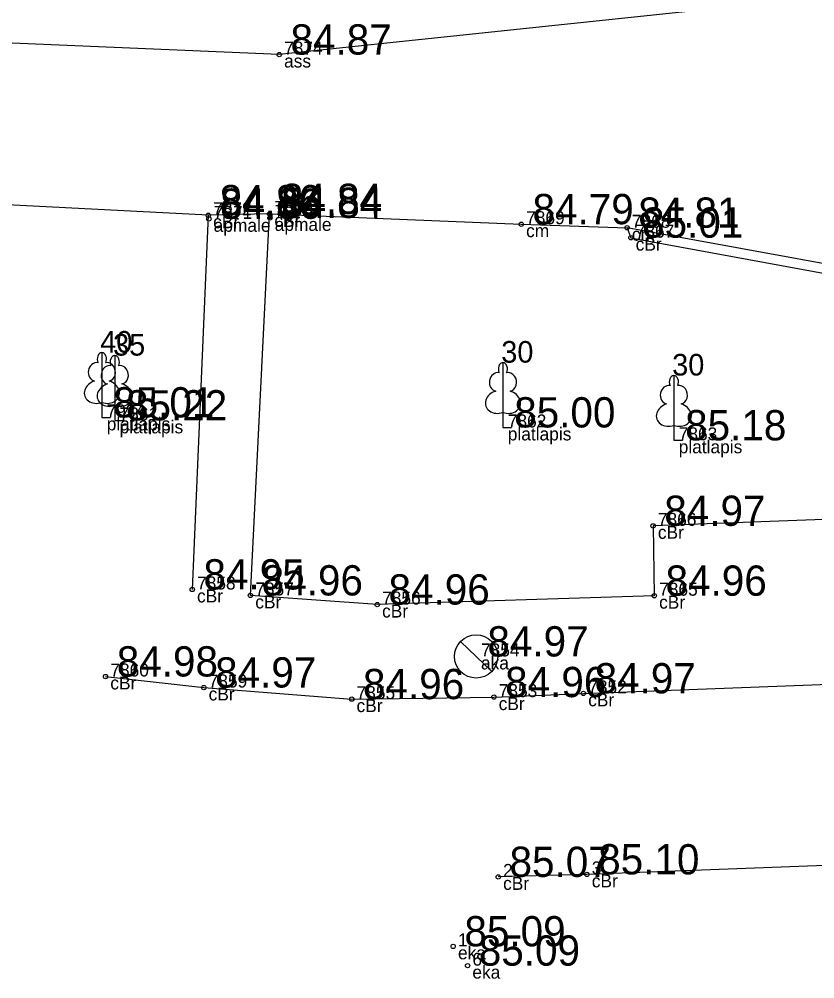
# Model space of a CAD drawing. Extents: x 614911 to 615803, y 262110 to 264311.
# Drawn here: x 615091.66 to 615110.07, y 262498.43 to 262520.64 of the extents above; entities that cross this region are included whole.
import ezdxf

# ---------------------------------------------------------------- set-up
doc = ezdxf.new("R2010")
doc.units = 0
for name, color, linetype in [('Level 1', 7, 'Continuous'), ('Level 12', 7, 'Continuous'), ('Level 37', 7, 'Continuous'), ('Level 53', 7, 'Continuous'), ('Level 54', 7, 'Continuous'), ('Level 57', 7, 'Continuous'), ('Level 58', 7, 'Continuous')]:
    doc.layers.add(name, color=color, linetype=linetype)

msp = doc.modelspace()

# ---------------------------------------------------------------- linework, layer by layer
at = {"layer": 'Level 1'}
for p, q in [((615093.575, 262511.768), (615093.575, 262511.421)), ((615093.873, 262511.699), (615093.873, 262511.352)), ((615102.855, 262511.536), (615102.855, 262511.189)), ((615093.575, 262511.421), (615093.775, 262511.421)), ((615093.873, 262511.352), (615094.073, 262511.352)), ((615102.855, 262511.189), (615103.055, 262511.189)), ((615106.81, 262511.238), (615106.81, 262510.891)), ((615106.81, 262510.891), (615107.01, 262510.891))]:
    msp.add_line(p, q, dxfattribs=at)
for points in [[(615093.575, 262512.921), (615093.575, 262511.768)], [(615093.873, 262512.852), (615093.873, 262511.699)], [(615093.665, 262512.689), (615093.664, 262512.69)], [(615093.963, 262512.62), (615093.962, 262512.621)], [(615102.855, 262512.689), (615102.855, 262511.536)], [(615102.945, 262512.457), (615102.944, 262512.458)], [(615106.81, 262512.391), (615106.81, 262511.238)], [(615106.9, 262512.159), (615106.899, 262512.16)]]:
    msp.add_lwpolyline(points, dxfattribs=at)
for centre, major_axis, ratio, start_param, end_param in [((615093.575, 262512.771), (0, -0.15), 0.707107, 3.14537, 5.287485), ((615093.575, 262512.771), (0, -0.15), 0.707107, 0.995701, 3.137816), ((615093.873, 262512.702), (0, -0.15), 0.707107, 3.14537, 5.287485), ((615093.873, 262512.702), (0, -0.15), 0.707107, 0.995701, 3.137816), ((615093.447, 262512.476), (-0.039, -0.212), 0.861323, 3.141593, 6.283185), ((615093.745, 262512.407), (-0.039, -0.212), 0.861323, 3.141593, 6.283185), ((615093.703, 262512.476), (0.039, -0.212), 0.861323, 0, 3.141593), ((615094.001, 262512.407), (0.039, -0.212), 0.861323, 0, 3.141593), ((615102.855, 262512.539), (0, -0.15), 0.707107, 3.14537, 5.287485), ((615102.855, 262512.539), (0, -0.15), 0.707107, 0.995701, 3.137816), ((615102.727, 262512.244), (-0.039, -0.212), 0.861323, 3.141593, 6.283185), ((615102.983, 262512.244), (0.039, -0.212), 0.861323, 0, 3.141593), ((615106.81, 262512.241), (0, -0.15), 0.707107, 3.14537, 5.287485), ((615106.81, 262512.241), (0, -0.15), 0.707107, 0.995701, 3.137816), ((615093.485, 262512.014), (0.307, 0.095), 0.814445, 1.570796, 4.752015), ((615093.783, 262511.945), (0.307, 0.095), 0.814445, 1.570796, 4.752015), ((615093.665, 262512.014), (-0.307, 0.095), 0.814445, 1.531171, 4.712389), ((615093.963, 262511.945), (-0.307, 0.095), 0.814445, 1.531171, 4.712389), ((615106.682, 262511.946), (-0.039, -0.212), 0.861323, 3.141593, 6.283185), ((615106.938, 262511.946), (0.039, -0.212), 0.861323, 0, 3.141593), ((615102.765, 262511.782), (0.307, 0.095), 0.814445, 1.570796, 4.752015), ((615102.945, 262511.782), (-0.307, 0.095), 0.814445, 1.531171, 4.712389), ((615106.72, 262511.484), (0.307, 0.095), 0.814445, 1.570796, 4.752015), ((615106.9, 262511.484), (-0.307, 0.095), 0.814445, 1.531171, 4.712389)]:
    msp.add_ellipse(centre, major_axis=major_axis, ratio=ratio, start_param=start_param, end_param=end_param, dxfattribs=at)
at = {"layer": 'Level 12'}
for p, q in [((615101.876, 262506.237), (615102.594, 262505.541)), ((615102.235, 262505.889), (615102.234, 262505.888))]:
    msp.add_line(p, q, dxfattribs=at)
msp.add_circle((615102.235, 262505.889), 0.5, dxfattribs=at)
at = {"layer": 'Level 37'}
for points in [[(615223.546, 262552.282), (615170.292, 262536.941), (615153.815, 262531.791), (615121.081, 262522.293), (615097.679, 262519.819), (615079.491, 262520.592), (615062.627, 262523.82), (615033.227, 262532.662), (615019.453, 262538.139)], [(615096.037, 262516.1), (615077.569, 262517.053), (615073.909, 262517.698), (615072.06, 262516.311), (615072.054, 262509.609)], [(615097.455, 262516.13), (615096.037, 262516.1), (615095.665, 262507.439)], [(615116.513, 262509.293), (615106.328, 262508.912), (615106.357, 262507.295), (615099.947, 262507.09), (615097.013, 262507.301), (615097.455, 262516.13), (615103.279, 262515.893), (615105.726, 262515.811)], [(615117.253, 262499.337), (615117.014, 262505.573), (615116.816, 262509.348), (615116.017, 262510.575), (615113.679, 262514.361), (615105.726, 262515.811), (615105.815, 262515.581), (615113.54, 262514.16), (615115.817, 262510.475), (615116.524, 262509.329), (615116.681, 262505.521)], [(615093.659, 262505.425), (615095.934, 262505.17), (615099.356, 262504.901), (615102.645, 262504.948), (615104.716, 262505.035), (615110.609, 262505.255), (615110.718, 262501.07), (615104.799, 262500.845), (615102.747, 262500.787)]]:
    msp.add_lwpolyline(points, dxfattribs=at)
at = {"layer": 'Level 57'}
for centre in [(615097.679, 262519.819), (615096.037, 262516.1), (615097.455, 262516.13), (615096.05, 262516.017), (615097.462, 262516.038), (615103.279, 262515.893), (615105.726, 262515.811), (615105.815, 262515.581), (615106.328, 262508.912), (615095.665, 262507.439), (615097.013, 262507.301), (615106.357, 262507.295), (615099.947, 262507.09), (615093.659, 262505.425), (615095.934, 262505.17), (615104.716, 262505.035), (615099.356, 262504.901), (615102.645, 262504.948), (615102.747, 262500.787), (615104.799, 262500.845), (615101.703, 262499.18), (615102.036, 262498.733)]:
    msp.add_circle(centre, 0.05, dxfattribs=at)
at = {"layer": 'Level 58'}
for centre in [(615097.679, 262519.819), (615096.037, 262516.1), (615097.455, 262516.13), (615096.05, 262516.017), (615097.462, 262516.038), (615103.279, 262515.893), (615105.726, 262515.811), (615105.815, 262515.581), (615106.328, 262508.912), (615095.665, 262507.439), (615097.013, 262507.301), (615106.357, 262507.295), (615099.947, 262507.09), (615093.659, 262505.425), (615095.934, 262505.17), (615104.716, 262505.035), (615099.356, 262504.901), (615102.645, 262504.948), (615102.747, 262500.787), (615104.799, 262500.845), (615101.703, 262499.18), (615102.036, 262498.733)]:
    msp.add_circle(centre, 0.05, dxfattribs=at)

# ---------------------------------------------------------------- texts
at = {"layer": 'Level 1'}
for s, p in [(' 40', (615093.35, 262512.921)), (' 35', (615093.648, 262512.852)), (' 30', (615102.63, 262512.689)), (' 30', (615106.585, 262512.391))]:
    msp.add_text(s, height=0.5, dxfattribs=at).set_placement(p)
at = {"layer": 'Level 53'}
for s, p in [(' ass', (615097.679, 262519.519)), (' cBr', (615096.037, 262515.8)), (' apmale', (615096.05, 262515.717)), (' cBr', (615097.455, 262515.83)), (' apmale', (615097.462, 262515.738)), (' cm', (615103.279, 262515.593)), (' cm', (615105.726, 262515.511)), (' cBr', (615105.815, 262515.281)), (' platlapis', (615093.575, 262511.121)), (' platlapis', (615093.873, 262511.052)), (' platlapis', (615102.855, 262510.889)), (' platlapis', (615106.81, 262510.591)), (' cBr', (615106.328, 262508.612)), (' cBr', (615095.665, 262507.139)), (' cBr', (615097.013, 262507.001)), (' cBr', (615106.357, 262506.995)), (' cBr', (615099.947, 262506.79)), (' aka', (615102.235, 262505.589)), (' cBr', (615093.659, 262505.125)), (' cBr', (615095.934, 262504.87)), (' cBr', (615104.716, 262504.735)), (' cBr', (615099.356, 262504.601)), (' cBr', (615102.645, 262504.648)), (' cBr', (615104.799, 262500.545)), (' cBr', (615102.747, 262500.487)), (' eka', (615101.703, 262498.88)), (' eka', (615102.036, 262498.433))]:
    msp.add_text(s, height=0.3, dxfattribs=at).set_placement(p)
at = {"layer": 'Level 54'}
for s, p in [(' 7874', (615097.679, 262519.819)), (' 7872', (615096.037, 262516.1)), (' 7873', (615097.455, 262516.13)), (' 7871', (615096.05, 262516.017)), (' 7870', (615097.462, 262516.038)), (' 7869', (615103.279, 262515.893)), (' 7868', (615105.726, 262515.811)), (' 7867', (615105.815, 262515.581)), (' 7934', (615093.575, 262511.421)), (' 7861', (615093.873, 262511.352)), (' 7862', (615102.855, 262511.189)), (' 7863', (615106.81, 262510.891)), (' 7866', (615106.328, 262508.912)), (' 7858', (615095.665, 262507.439)), (' 7857', (615097.013, 262507.301)), (' 7865', (615106.357, 262507.295)), (' 7856', (615099.947, 262507.09)), (' 7854', (615102.235, 262505.889)), (' 7860', (615093.659, 262505.425)), (' 7859', (615095.934, 262505.17)), (' 7852', (615104.716, 262505.035)), (' 7855', (615099.356, 262504.901)), (' 7853', (615102.645, 262504.948)), (' 2', (615102.747, 262500.787)), (' 3', (615104.799, 262500.845)), (' 1', (615101.703, 262499.18)), (' 6', (615102.036, 262498.733))]:
    msp.add_text(s, height=0.3, dxfattribs=at).set_placement(p)
at = {"layer": 'Level 58'}
for s, p in [(' 84.87', (615097.679, 262519.819)), (' 84.86', (615096.037, 262516.1)), (' 84.84', (615097.455, 262516.13)), (' 84.86', (615096.05, 262516.017)), (' 84.84', (615097.462, 262516.038)), (' 84.79', (615103.279, 262515.893)), (' 84.81', (615105.726, 262515.811)), (' 85.01', (615105.815, 262515.581)), (' 85.01', (615093.575, 262511.421)), (' 85.22', (615093.873, 262511.352)), (' 85.00', (615102.855, 262511.189)), (' 85.18', (615106.81, 262510.891)), (' 84.97', (615106.328, 262508.912)), (' 84.95', (615095.665, 262507.439)), (' 84.96', (615097.013, 262507.301)), (' 84.96', (615106.357, 262507.295)), (' 84.96', (615099.947, 262507.09)), (' 84.97', (615102.235, 262505.889)), (' 84.98', (615093.659, 262505.425)), (' 84.97', (615095.934, 262505.17)), (' 84.97', (615104.716, 262505.035)), (' 84.96', (615099.356, 262504.901)), (' 84.96', (615102.645, 262504.948)), (' 85.07', (615102.747, 262500.787)), (' 85.10', (615104.799, 262500.845)), (' 85.09', (615101.703, 262499.18)), (' 85.09', (615102.036, 262498.733))]:
    msp.add_text(s, height=0.7, dxfattribs=at).set_placement(p)

doc.saveas('drawing.dxf')
